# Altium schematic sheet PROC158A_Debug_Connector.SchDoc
size 431 x 279 mm; Date: Not shown in title block; ApprovedBy: Not shown in title block; CheckedBy: Not shown in title block; Author: Not shown in title block; CompanyName: Not shown in title block; Engineer: Not shown in title block; Organization: Not shown in title block; Address1: Not shown in title block; Address2: Not shown in title block; Address3: Not shown in title block; Address4: Not shown in title block; DocumentNumber: 21; Revision: Use project parameter SCH_Rev; SheetNumber: 21; SheetTotal: 24; PageSetup: Record=PageOptions¦CenterHorizontal=True¦CenterVertical=True¦PrintScale=1.00¦XCorrection=1.00¦YCorrection=1.00¦PrintKind=0¦BorderSize=5000000¦LeftOffset=0¦BottomOffset=0¦Orientation=2¦PaperLength=1000¦PaperWidth=1000¦Scale=100¦PaperSource=15¦PrintQuality=600¦MediaType=1¦DitherType=10¦PaperKind=Letter¦PrintScaleMode=1
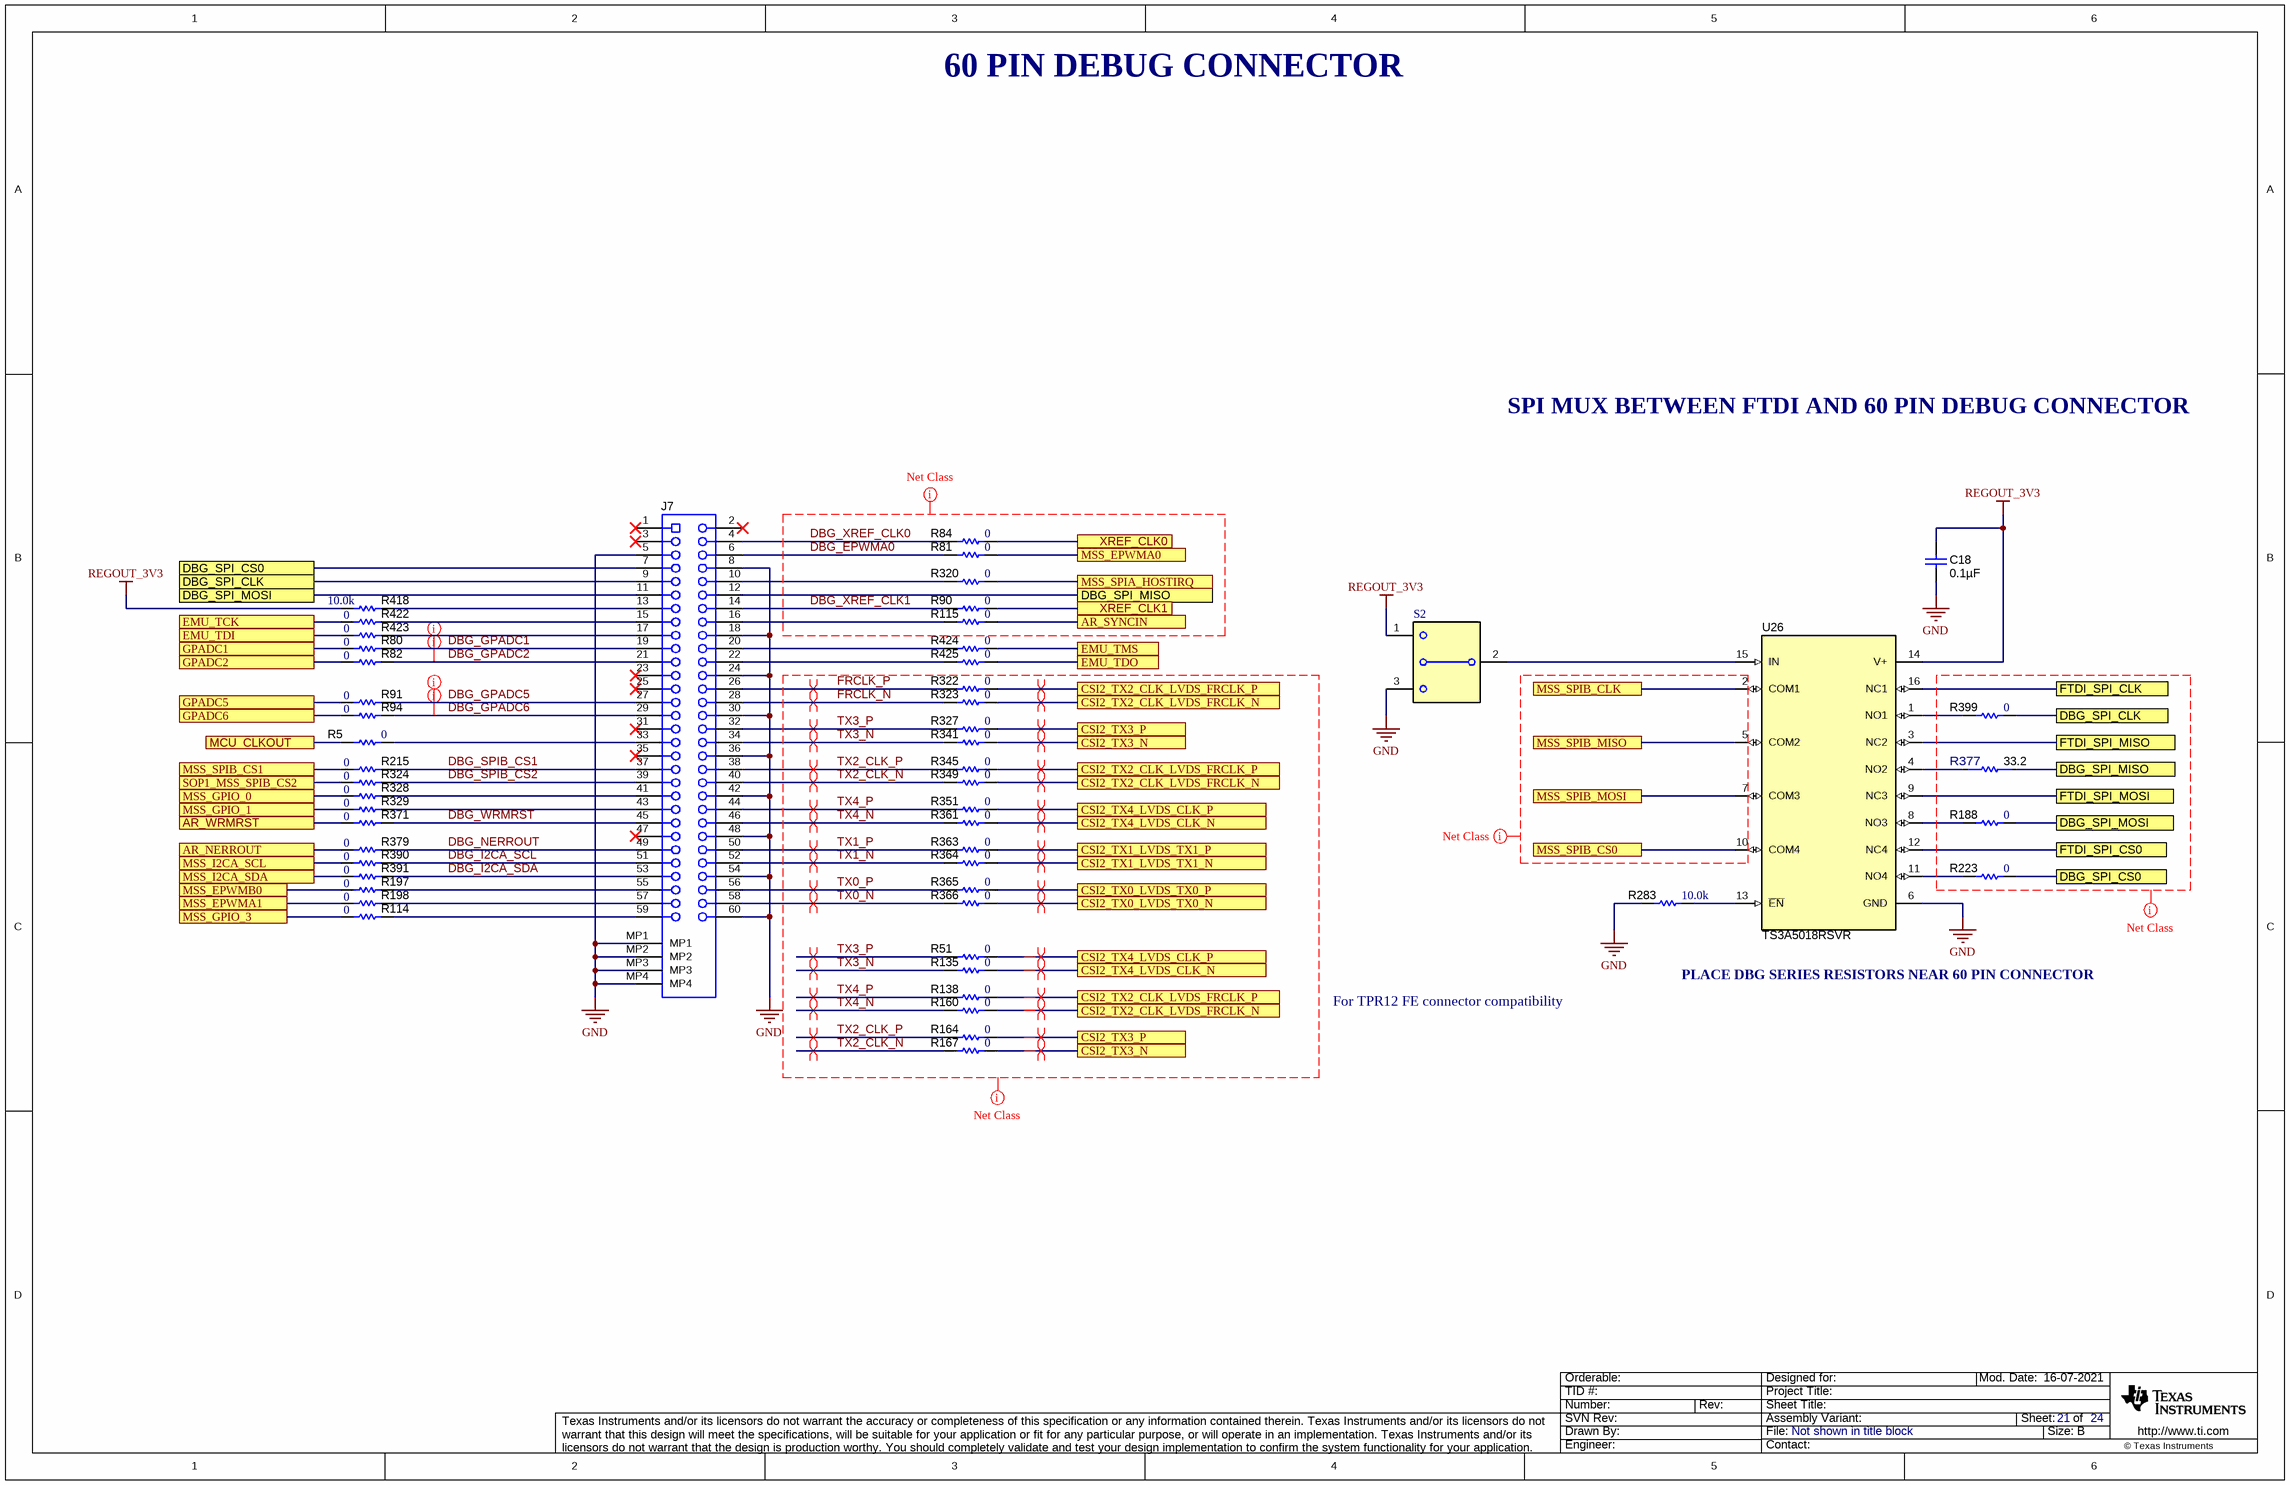
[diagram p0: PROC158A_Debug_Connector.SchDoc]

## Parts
C18  ValueDisplayed: 0.1µF  [0402L]  (hidden comment: C0402C104K8RACTU)
J7  QSH-030-01-L-D-A  [Samtec_QSH-030-01-X-D-A]  (value not drawn)
R5  ValueDisplayed: 0  [0201L]  (hidden comment: CRCW02010000Z0ED)
R51  ValueDisplayed: 0  [0201L]  (hidden comment: CRCW02010000Z0ED)
R80  ValueDisplayed: 0  [0201L]  (hidden comment: CRCW02010000Z0ED)
R81  ValueDisplayed: 0  [0201L]  (hidden comment: CRCW02010000Z0ED)
R82  ValueDisplayed: 0  [0201L]  (hidden comment: CRCW02010000Z0ED)
R84  ValueDisplayed: 0  [0201L]  (hidden comment: CRCW02010000Z0ED)
R90  ValueDisplayed: 0  [0201L]  (hidden comment: CRCW02010000Z0ED)
R91  ValueDisplayed: 0  [0201L]  (hidden comment: CRCW02010000Z0ED)
R94  ValueDisplayed: 0  [0201L]  (hidden comment: CRCW02010000Z0ED)
R114  ValueDisplayed: 0  [0201L]  (hidden comment: CRCW02010000Z0ED)
R115  ValueDisplayed: 0  [0201L]  (hidden comment: CRCW02010000Z0ED)
R135  ValueDisplayed: 0  [0201L]  (hidden comment: CRCW02010000Z0ED)
R138  ValueDisplayed: 0  [0201L]  (hidden comment: CRCW02010000Z0ED)
R160  ValueDisplayed: 0  [0201L]  (hidden comment: CRCW02010000Z0ED)
R164  ValueDisplayed: 0  [0201L]  (hidden comment: CRCW02010000Z0ED)
R167  ValueDisplayed: 0  [0201L]  (hidden comment: CRCW02010000Z0ED)
R188  ValueDisplayed: 0  [0201L]  (hidden comment: CRCW02010000Z0ED)
R197  ValueDisplayed: 0  [0201L]  (hidden comment: CRCW02010000Z0ED)
R198  ValueDisplayed: 0  [0201L]  (hidden comment: CRCW02010000Z0ED)
R215  ValueDisplayed: 0  [0201L]  (hidden comment: CRCW02010000Z0ED)
R223  ValueDisplayed: 0  [0201L]  (hidden comment: CRCW02010000Z0ED)
R283  ValueDisplayed: 10.0k  [0402L]  (hidden comment: CRCW040210K0FKED)
R320  ValueDisplayed: 0  [0201L]  (hidden comment: CRCW02010000Z0ED)
R322  ValueDisplayed: 0  [0201L]  (hidden comment: CRCW02010000Z0ED)
R323  ValueDisplayed: 0  [0201L]  (hidden comment: CRCW02010000Z0ED)
R324  ValueDisplayed: 0  [0201L]  (hidden comment: CRCW02010000Z0ED)
R327  ValueDisplayed: 0  [0201L]  (hidden comment: CRCW02010000Z0ED)
R328  ValueDisplayed: 0  [0201L]  (hidden comment: CRCW02010000Z0ED)
R329  ValueDisplayed: 0  [0201L]  (hidden comment: CRCW02010000Z0ED)
R341  ValueDisplayed: 0  [0201L]  (hidden comment: CRCW02010000Z0ED)
R345  ValueDisplayed: 0  [0201L]  (hidden comment: CRCW02010000Z0ED)
R349  ValueDisplayed: 0  [0201L]  (hidden comment: CRCW02010000Z0ED)
R351  ValueDisplayed: 0  [0201L]  (hidden comment: CRCW02010000Z0ED)
R361  ValueDisplayed: 0  [0201L]  (hidden comment: CRCW02010000Z0ED)
R363  ValueDisplayed: 0  [0201L]  (hidden comment: CRCW02010000Z0ED)
R364  ValueDisplayed: 0  [0201L]  (hidden comment: CRCW02010000Z0ED)
R365  ValueDisplayed: 0  [0201L]  (hidden comment: CRCW02010000Z0ED)
R366  ValueDisplayed: 0  [0201L]  (hidden comment: CRCW02010000Z0ED)
R371  ValueDisplayed: 0  [0201L]  (hidden comment: CRCW02010000Z0ED)
R377  Res_ohm: 33.2  [FP-ERJ-1GNF33R2C_0201-MFG]  (hidden comment: ERJ-1GNF33R2C)
R379  ValueDisplayed: 0  [0201L]  (hidden comment: CRCW02010000Z0ED)
R390  ValueDisplayed: 0  [0201L]  (hidden comment: CRCW02010000Z0ED)
R391  ValueDisplayed: 0  [0201L]  (hidden comment: CRCW02010000Z0ED)
R399  ValueDisplayed: 0  [0201L]  (hidden comment: CRCW02010000Z0ED)
R418  ValueDisplayed: 10.0k  [0402L]  (hidden comment: CRCW040210K0FKED)
R422  ValueDisplayed: 0  [0201L]  (hidden comment: CRCW02010000Z0ED)
R423  ValueDisplayed: 0  [0201L]  (hidden comment: CRCW02010000Z0ED)
R424  ValueDisplayed: 0  [0201L]  (hidden comment: CRCW02010000Z0ED)
R425  ValueDisplayed: 0  [0201L]  (hidden comment: CRCW02010000Z0ED)
S2  CJS-1201TA  [SW_CJS_1201A]  (value not drawn)
U26  TS3A5018RSVR  [RSV0016A]

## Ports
AR_NERROUT, AR_SYNCIN, AR_WRMRST, CSI2_TX0_LVDS_TX0_N, CSI2_TX0_LVDS_TX0_P, CSI2_TX1_LVDS_TX1_N, CSI2_TX1_LVDS_TX1_P, CSI2_TX2_CLK_LVDS_FRCLK_N, CSI2_TX2_CLK_LVDS_FRCLK_P, CSI2_TX3_N, CSI2_TX3_P, CSI2_TX4_LVDS_CLK_N, CSI2_TX4_LVDS_CLK_P, DBG_SPI_CLK, DBG_SPI_CS0, DBG_SPI_MISO, DBG_SPI_MOSI, EMU_TCK, EMU_TDI, EMU_TDO, EMU_TMS, FTDI_SPI_CLK, FTDI_SPI_CS0, FTDI_SPI_MISO, FTDI_SPI_MOSI, GPADC1, GPADC2, GPADC5, GPADC6, MCU_CLKOUT, MSS_EPWMA0, MSS_EPWMA1, MSS_EPWMB0, MSS_GPIO_0, MSS_GPIO_1, MSS_GPIO_3, MSS_I2CA_SCL, MSS_I2CA_SDA, MSS_SPIA_HOSTIRQ, MSS_SPIB_CLK, MSS_SPIB_CS0, MSS_SPIB_CS1, MSS_SPIB_MISO, MSS_SPIB_MOSI, SOP1_MSS_SPIB_CS2, XREF_CLK0, XREF_CLK1

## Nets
GND: C18.1 J7.5 J7.8 J7.18 J7.24 J7.30 J7.36 J7.42 J7.48 J7.54 J7.60 J7.MP1 J7.MP2 J7.MP3 J7.MP4 R283.2 S2.3 U26.6(GND)
REGOUT_3V3: C18.2 R418.2 S2.1 U26.14(V+)
AR_NERROUT: R379.1 ; port AR_NERROUT
AR_SYNCIN: R115.1 ; port AR_SYNCIN
AR_WRMRST: R371.1 ; port AR_WRMRST
CSI2_TX0_LVDS_TX0_N: R366.2 ; port CSI2_TX0_LVDS_TX0_N
CSI2_TX0_LVDS_TX0_P: R365.2 ; port CSI2_TX0_LVDS_TX0_P
CSI2_TX1_LVDS_TX1_N: R364.2 ; port CSI2_TX1_LVDS_TX1_N
CSI2_TX1_LVDS_TX1_P: R363.2 ; port CSI2_TX1_LVDS_TX1_P
CSI2_TX2_CLK_LVDS_FRCLK_N: R160.2 R323.2 R349.2 ; port CSI2_TX2_CLK_LVDS_FRCLK_N
CSI2_TX2_CLK_LVDS_FRCLK_P: R138.2 R322.2 R345.2 ; port CSI2_TX2_CLK_LVDS_FRCLK_P
CSI2_TX3_N: R167.2 R341.2 ; port CSI2_TX3_N
CSI2_TX3_P: R164.2 R327.2 ; port CSI2_TX3_P
CSI2_TX4_LVDS_CLK_N: R135.2 R361.2 ; port CSI2_TX4_LVDS_CLK_N
CSI2_TX4_LVDS_CLK_P: R51.2 R351.2 ; port CSI2_TX4_LVDS_CLK_P
DBG_EPWMA0: J7.6 R81.2
DBG_GPADC1: J7.19 R80.2
DBG_GPADC2: J7.21 R82.2
DBG_GPADC5: J7.27 R91.2
DBG_GPADC6: J7.29 R94.2
DBG_I2CA_SCL: J7.51 R390.2
DBG_I2CA_SDA: J7.53 R391.2
DBG_NERROUT: J7.49 R379.2
DBG_SPI_CLK: J7.9 R399.2 ; port DBG_SPI_CLK
DBG_SPI_CS0: J7.7 R223.2 ; port DBG_SPI_CS0
DBG_SPI_MISO: J7.12 R377.1 ; port DBG_SPI_MISO
DBG_SPI_MOSI: J7.11 R188.2 ; port DBG_SPI_MOSI
DBG_SPIB_CS1: J7.37 R215.2
DBG_SPIB_CS2: J7.39 R324.2
DBG_WRMRST: J7.45 R371.2
DBG_XREF_CLK0: J7.4 R84.2
DBG_XREF_CLK1: J7.14 R90.2
EMU_TCK: R422.1 ; port EMU_TCK
EMU_TDI: R423.1 ; port EMU_TDI
EMU_TDO: R425.2 ; port EMU_TDO
EMU_TMS: R424.2 ; port EMU_TMS
FRCLK_N: J7.28 R323.1
FRCLK_P: J7.26 R322.1
FTDI_SPI_CLK: U26.16(NC1) ; port FTDI_SPI_CLK
FTDI_SPI_CS0: U26.12(NC4) ; port FTDI_SPI_CS0
FTDI_SPI_MISO: U26.3(NC2) ; port FTDI_SPI_MISO
FTDI_SPI_MOSI: U26.9(NC3) ; port FTDI_SPI_MOSI
GPADC1: R80.1 ; port GPADC1
GPADC2: R82.1 ; port GPADC2
GPADC5: R91.1 ; port GPADC5
GPADC6: R94.1 ; port GPADC6
MCU_CLKOUT: R5.2 ; port MCU_CLKOUT
MSS_EPWMA0: R81.1 ; port MSS_EPWMA0
MSS_EPWMA1: R198.1 ; port MSS_EPWMA1
MSS_EPWMB0: R197.1 ; port MSS_EPWMB0
MSS_GPIO_0: R328.1 ; port MSS_GPIO_0
MSS_GPIO_1: R329.1 ; port MSS_GPIO_1
MSS_GPIO_3: R114.1 ; port MSS_GPIO_3
MSS_I2CA_SCL: R390.1 ; port MSS_I2CA_SCL
MSS_I2CA_SDA: R391.1 ; port MSS_I2CA_SDA
MSS_SPIA_HOSTIRQ: R320.1 ; port MSS_SPIA_HOSTIRQ
MSS_SPIB_CLK: U26.2(COM1) ; port MSS_SPIB_CLK
MSS_SPIB_CS0: U26.10(COM4) ; port MSS_SPIB_CS0
MSS_SPIB_CS1: R215.1 ; port MSS_SPIB_CS1
MSS_SPIB_MISO: U26.5(COM2) ; port MSS_SPIB_MISO
MSS_SPIB_MOSI: U26.7(COM3) ; port MSS_SPIB_MOSI
SOP1_MSS_SPIB_CS2: R324.1 ; port SOP1_MSS_SPIB_CS2
TX0_N: J7.58 R366.1
TX0_P: J7.56 R365.1
TX1_N: J7.52 R364.1
TX1_P: J7.50 R363.1
TX2_CLK_N: J7.40 R167.1 R349.1
TX2_CLK_P: J7.38 R164.1 R345.1
TX3_N: J7.34 R135.1 R341.1
TX3_P: J7.32 R51.1 R327.1
TX4_N: J7.46 R160.1 R361.1
TX4_P: J7.44 R138.1 R351.1
XREF_CLK0: R84.1 ; port XREF_CLK0
XREF_CLK1: R90.1 ; port XREF_CLK1
NetJ7_10: J7.10 R320.2
NetJ7_13: J7.13 R418.1
NetJ7_15: J7.15 R422.2
NetJ7_16: J7.16 R115.2
NetJ7_17: J7.17 R423.2
NetJ7_20: J7.20 R424.1
NetJ7_22: J7.22 R425.1
NetJ7_33: J7.33 R5.1
NetJ7_41: J7.41 R328.2
NetJ7_43: J7.43 R329.2
NetJ7_55: J7.55 R197.2
NetJ7_57: J7.57 R198.2
NetJ7_59: J7.59 R114.2
NetR188_1: R188.1 U26.8(NO3)
NetR223_1: R223.1 U26.11(NO4)
NetR283_1: R283.1 U26.13(~{EN})
NetR377_2: R377.2 U26.4(NO2)
NetR399_1: R399.1 U26.1(NO1)
NetS2_2: S2.2(COM) U26.15(IN)

Not connected (* = marked no-connect by the designer): J7 1* 2* 3* 23* 25* 31* 35* 47*

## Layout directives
net class CSI: FRCLK_N, FRCLK_P, TX0_N, TX0_P, TX1_N, TX1_P, TX2_CLK_N, TX2_CLK_P, TX3_N, TX3_P, TX4_N, TX4_P
net class CLKOUT: DBG_EPWMA0, DBG_XREF_CLK0, DBG_XREF_CLK1
net class JTAG: (no net found under the mark)
net class GPADC: DBG_GPADC1, DBG_GPADC2, DBG_GPADC5, DBG_GPADC6
differential pair: CSI2_TX0_LVDS_TX0_N, CSI2_TX0_LVDS_TX0_P, CSI2_TX1_LVDS_TX1_N, CSI2_TX1_LVDS_TX1_P, CSI2_TX2_CLK_LVDS_FRCLK_N, CSI2_TX2_CLK_LVDS_FRCLK_P, CSI2_TX3_N, CSI2_TX3_P, CSI2_TX4_LVDS_CLK_N, CSI2_TX4_LVDS_CLK_P, FRCLK_N, FRCLK_P, TX0_N, TX0_P, TX1_N, TX1_P, TX2_CLK_N, TX2_CLK_P, TX3_N, TX3_P, TX4_N, TX4_P

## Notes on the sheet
- 60 PIN DEBUG CONNECTOR
- SPI MUX BETWEEN FTDI AND 60 PIN DEBUG CONNECTOR
- For TPR12 FE connector compatibility
- PLACE DBG SERIES RESISTORS NEAR 60 PIN CONNECTOR

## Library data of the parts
C18 = CMP-0078241-1: CAP, CERM, 0.1 µF, 10 V,+/- 10%, X7R, 0402; Manufacturer: Kemet; TaMin_C: -55°C; Polarized: N; SizeAreaWB_mm2: 3; U/M: EA; Value: 0.1uF; TaMax_C: 125°C; SizeZ_mm: 0.6; SizeX_mm: 1; SizeY_mm: 0.5; Cap_Case: 0402; Value2: 10V; Cap_F: 100nF; AEC Category: Q200
J7 = CMP-0075524-1: Receptacle, 0.5 mm, 30x2, Gold, TH; Manufacturer: Samtec; Pitch_mm: 0.5; Gender: Female; Green_REACh: Passed; CT: False; Shrouded: N; RowSpacing_mm: 5.73; Green_Lifecycle: Active; Row_Count: 2
R5 R51 R80-R82 R84 R90 R91 R94 R114 R115 R135 R138 R160 R164 R167 R188 R197 R198 R215 R223 R320 R322-R324 R327-R329 R341 R345 R349 R351 R361 R363-R366 R371 R379 R390 R391 R399 R422-R425 = CMP-0027008-4: RES, 0, 5%, 0.05 W, 0201; Manufacturer: Vishay-Dale; Power_W: 50mW; TempCo: ppm/C; Value_Code: 0000; Value: 0; EIA_Code: E24; SizeX_mm: 0.6; SizeY_mm: 0.3; SizeZ_mm: 0.26; Value2: 0.05W; SizeArea_mm2: 0.18; AEC Qualified: N; AEC Category: Q200
R283 R418 = CMP-0025958-3: RES, 10.0 k, 1%, 0.063 W, AEC-Q200 Grade 0, 0402; Manufacturer: Vishay-Dale; Power_W: 63mW; TempCo: 100 ppm/C; Value_Code: 10k0; Value: 10.0k; EIA_Code: E96; Res_ohm: 10k; SizeX_mm: 1; SizeY_mm: 0.5; SizeZ_mm: 0.6; Value2: 0.063W; AEC Qualified: Y; VDC_V: 50V; AEC Category: Q200; AEC Grade: 0
R377 = CMP-0089575-2: Res Thick Film 0201 33.2 Ohm 1% 0.05W(1/20W) ±200ppm/C Pad SMD Automotive T/R; Manufacturer: Panasonic; TempCo: 200ppm/°C; VDC_V: 25V; AEC Qualified: Yes; SizeZ_mm: 0.26mm; Power_W: 50mW; AEC Grade: Grade 1; Value: 33.2
S2 = CMP-0002159-2: Slide SW, SPDT 0.1A 50VDC; Manufacturer: Copal Electronics; CurrentRating_mA: 100A; SwitchFunction: On-Off-On; VDC_V: 50V; PositionCount: 1; CompType: Switch
U26 = CMP-0067415-1: 10-Ohm Quad SPDT Analog Switch, RSV0016A (UQFN-16); Alternate Manufacturer: Texas Instruments; SizeAreaWB_mm2: 10.08; U/M: EA; SizeZ_mm: 0.55; SizeX_mm: 1.8; SizeY_mm: 2.6; SizeArea_mm2: 4.68; CompType: IC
